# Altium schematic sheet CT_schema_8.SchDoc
size 147 x 119 mm
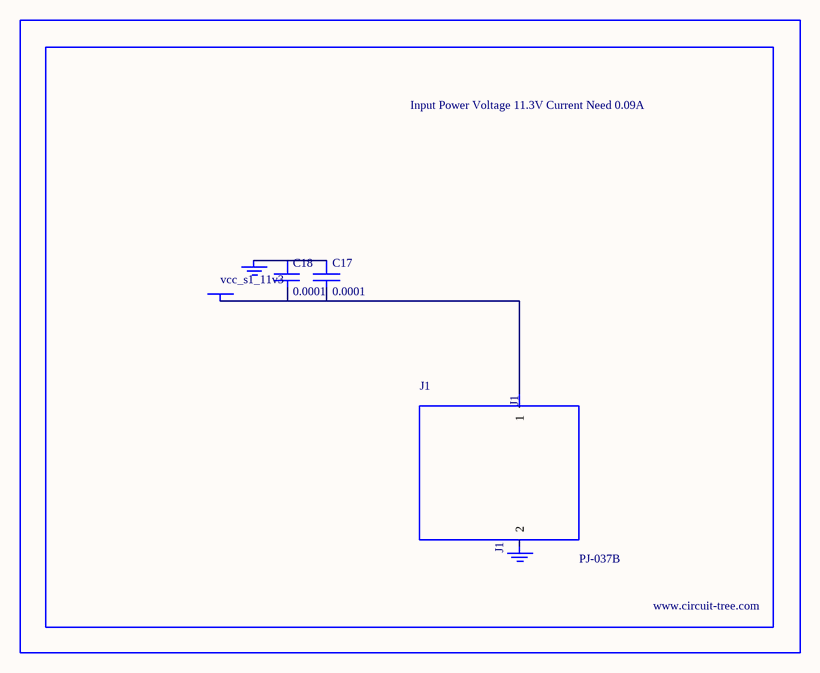
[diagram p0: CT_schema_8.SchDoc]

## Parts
BORDER7  (no value)
C17  0.0001  [EXV-9H]
C18  0.0001  [EXV-9H]
GND_INSTANCE_7_0  (no value)
GND_INSTANCE_7_1  (no value)
J1  PJ-037B  [PJ-037B_PACKAGE]
POWER_INSTANCE_7_0  vcc_s1_11v3

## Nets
NetC17_1: C17.1 C18.1 GND_INSTANCE_7_0.0(GND)
NetC17_2: C17.2 C18.2 J1.1 POWER_INSTANCE_7_0.0(PWR)

Not connected (* = marked no-connect by the designer): GND_INSTANCE_7_1 0(GND); J1 2

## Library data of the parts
BORDER7 = BORDER_PAGE7
C17 C18 = EDK107M035A9HAA
GND_INSTANCE_7_0 GND_INSTANCE_7_1 = GND
POWER_INSTANCE_7_0 = PWR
